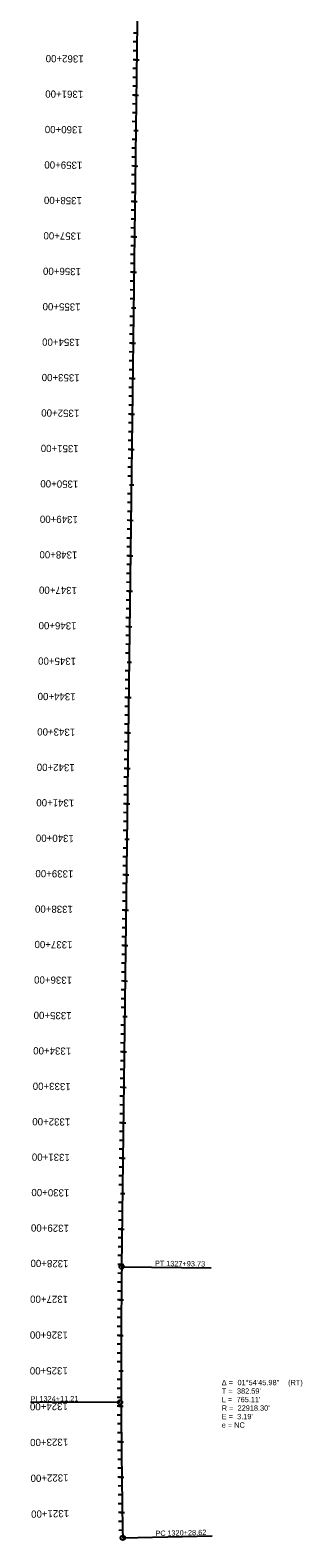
# Model space of a CAD drawing. Extents: x 20505176 to 20507119, y 7960287 to 7982631.
# Drawn here: x 20506353 to 20507119, y 7964831 to 7969085 of the extents above; entities that cross this region are included whole.
import ezdxf

# ---------------------------------------------------------------- set-up
doc = ezdxf.new("R2010")
doc.units = 0
for name, color, linetype in [('Alignment', 7, 'Continuous'), ('Default', 7, 'Continuous'), ('PC_REBAR GL 1', 7, 'Continuous'), ('TextAlignment', 7, 'Continuous'), ('TextAlignmentLrg', 7, 'Continuous'), ('TextAlignmentSml', 7, 'Continuous')]:
    doc.layers.add(name, color=color, linetype=linetype)

msp = doc.modelspace()

# ---------------------------------------------------------------- linework, layer by layer
at = {"layer": 'Alignment'}
msp.add_line((20506611.2, 7965595.6), (20506708.1, 7973298), dxfattribs=at)
msp.add_arc((20529527.7, 7965307.2), 22918.3, 179.27906, 181.19184, dxfattribs=at)
at = {"layer": 'Default'}
msp.add_line((20506611.2, 7965595.6), (20506708.1, 7973298), dxfattribs=at)
msp.add_arc((20529527.7, 7965307.2), 22918.3, 179.27906, 181.19184, dxfattribs=at)
at = {"layer": 'PC_REBAR GL 1'}
msp.add_line((20506611.2, 7965595.6), (20506708.1, 7973298), dxfattribs=at)
msp.add_arc((20529527.7, 7965307.2), 22918.3, 179.27906, 181.19184, dxfattribs=at)
at = {"layer": 'TextAlignment'}
for p, q in [((20506611.2, 7965595.6), (20506863.2, 7965592.4)), ((20506863.2, 7965592.4), (20506863.2, 7965592.4)), ((20506606.4, 7965213), (20506354.4, 7965212)), ((20506354.4, 7965212), (20506354.4, 7965212)), ((20506614.3, 7964830.5), (20506866.3, 7964835.8)), ((20506866.3, 7964835.8), (20506866.3, 7964835.8))]:
    msp.add_line(p, q, dxfattribs=at)
for centre in [(20506611.2, 7965595.6), (20506606.4, 7965213), (20506614.3, 7964830.5)]:
    msp.add_circle(centre, 6.24, dxfattribs=at)
at = {"layer": 'TextAlignmentLrg'}
for p, q in [((20506654, 7969001.6), (20506643.1, 7969001.7)), ((20506652.8, 7968901.6), (20506641.9, 7968901.8)), ((20506645.4, 7968801.7), (20506657.6, 7968801.5)), ((20506650.3, 7968701.6), (20506639.3, 7968701.8)), ((20506649, 7968601.6), (20506638.1, 7968601.8)), ((20506647.8, 7968501.6), (20506636.8, 7968501.8)), ((20506646.5, 7968401.7), (20506635.6, 7968401.8)), ((20506639.1, 7968301.7), (20506651.4, 7968301.6)), ((20506644, 7968201.7), (20506633.1, 7968201.8)), ((20506642.7, 7968101.7), (20506631.8, 7968101.8)), ((20506641.5, 7968001.7), (20506630.5, 7968001.8)), ((20506640.2, 7967901.7), (20506629.3, 7967901.8)), ((20506632.8, 7967801.8), (20506645.1, 7967801.6)), ((20506637.7, 7967701.7), (20506626.8, 7967701.8)), ((20506636.4, 7967601.7), (20506625.5, 7967601.9)), ((20506635.2, 7967501.7), (20506624.3, 7967501.9)), ((20506633.9, 7967401.7), (20506623, 7967401.9)), ((20506626.5, 7967301.8), (20506638.8, 7967301.7)), ((20506631.4, 7967201.7), (20506620.5, 7967201.9)), ((20506630.1, 7967101.8), (20506619.2, 7967101.9)), ((20506628.9, 7967001.8), (20506618, 7967001.9)), ((20506627.6, 7966901.8), (20506616.7, 7966901.9)), ((20506620.2, 7966801.9), (20506632.5, 7966801.7)), ((20506625.1, 7966701.8), (20506614.2, 7966701.9)), ((20506623.8, 7966601.8), (20506612.9, 7966601.9)), ((20506622.6, 7966501.8), (20506611.7, 7966501.9)), ((20506621.3, 7966401.8), (20506610.4, 7966402)), ((20506614, 7966301.9), (20506626.2, 7966301.7)), ((20506618.8, 7966201.8), (20506607.9, 7966202)), ((20506617.6, 7966101.8), (20506606.6, 7966102)), ((20506616.3, 7966001.8), (20506605.4, 7966002)), ((20506615, 7965901.9), (20506604.1, 7965902)), ((20506607.7, 7965801.9), (20506619.9, 7965801.8)), ((20506612.5, 7965701.9), (20506601.6, 7965702)), ((20506611.3, 7965601.9), (20506600.3, 7965602)), ((20506610.2, 7965501.9), (20506599.3, 7965502)), ((20506609.6, 7965401.9), (20506598.6, 7965401.9)), ((20506603.3, 7965301.9), (20506615.5, 7965301.9)), ((20506609.6, 7965201.9), (20506598.7, 7965201.8)), ((20506610.3, 7965101.9), (20506599.4, 7965101.8)), ((20506611.4, 7965001.9), (20506600.5, 7965001.7)), ((20506613, 7964901.9), (20506602, 7964901.7))]:
    msp.add_line(p, q, dxfattribs=at)
at = {"layer": 'TextAlignmentSml'}
for p, q in [((20506654.7, 7969051.6), (20506643.8, 7969051.7)), ((20506655, 7969076.6), (20506644.1, 7969076.7)), ((20506654.4, 7969026.6), (20506643.4, 7969026.7)), ((20506653.7, 7968976.6), (20506642.8, 7968976.7)), ((20506647.9, 7969001.7), (20506660.2, 7969001.5)), ((20506653.1, 7968926.6), (20506642.2, 7968926.8)), ((20506653.4, 7968951.6), (20506642.5, 7968951.7)), ((20506646.7, 7968901.7), (20506658.9, 7968901.5)), ((20506652.2, 7968851.6), (20506641.2, 7968851.8)), ((20506652.5, 7968876.6), (20506641.6, 7968876.8)), ((20506651.8, 7968826.6), (20506640.9, 7968826.8)), ((20506645.4, 7968801.7), (20506657.6, 7968801.5)), ((20506651.2, 7968776.6), (20506640.3, 7968776.8)), ((20506650.6, 7968726.6), (20506639.7, 7968726.8)), ((20506650.9, 7968751.6), (20506640, 7968751.8)), ((20506650, 7968676.6), (20506639, 7968676.8)), ((20506644.1, 7968701.7), (20506656.4, 7968701.6)), ((20506649.3, 7968626.6), (20506638.4, 7968626.8)), ((20506649.6, 7968651.6), (20506638.7, 7968651.8)), ((20506642.9, 7968601.7), (20506655.1, 7968601.6)), ((20506648.4, 7968551.6), (20506637.5, 7968551.8)), ((20506648.7, 7968576.6), (20506637.8, 7968576.8)), ((20506648.1, 7968526.6), (20506637.1, 7968526.8)), ((20506641.6, 7968501.7), (20506653.9, 7968501.6)), ((20506647.4, 7968476.6), (20506636.5, 7968476.8)), ((20506646.8, 7968426.7), (20506635.9, 7968426.8)), ((20506647.1, 7968451.7), (20506636.2, 7968451.8)), ((20506646.2, 7968376.7), (20506635.3, 7968376.8)), ((20506640.4, 7968401.7), (20506652.6, 7968401.6)), ((20506645.9, 7968351.7), (20506634.9, 7968351.8)), ((20506645.5, 7968326.7), (20506634.6, 7968326.8)), ((20506639.1, 7968301.7), (20506651.4, 7968301.6)), ((20506644.6, 7968251.7), (20506633.7, 7968251.8)), ((20506644.9, 7968276.7), (20506634, 7968276.8)), ((20506644.3, 7968226.7), (20506633.4, 7968226.8)), ((20506637.9, 7968201.7), (20506650.1, 7968201.6)), ((20506643.7, 7968176.7), (20506632.7, 7968176.8)), ((20506643, 7968126.7), (20506632.1, 7968126.8)), ((20506643.3, 7968151.7), (20506632.4, 7968151.8)), ((20506642.4, 7968076.7), (20506631.5, 7968076.8)), ((20506636.6, 7968101.8), (20506648.8, 7968101.6)), ((20506642.1, 7968051.7), (20506631.2, 7968051.8)), ((20506641.8, 7968026.7), (20506630.9, 7968026.8)), ((20506635.3, 7968001.8), (20506647.6, 7968001.6)), ((20506640.8, 7967951.7), (20506629.9, 7967951.8)), ((20506641.1, 7967976.7), (20506630.2, 7967976.8)), ((20506640.5, 7967926.7), (20506629.6, 7967926.8)), ((20506634.1, 7967901.8), (20506646.3, 7967901.6)), ((20506639.9, 7967876.7), (20506629, 7967876.8)), ((20506639.3, 7967826.7), (20506628.3, 7967826.8)), ((20506639.6, 7967851.7), (20506628.7, 7967851.8)), ((20506638.6, 7967776.7), (20506627.7, 7967776.8)), ((20506632.8, 7967801.8), (20506645.1, 7967801.6)), ((20506638.3, 7967751.7), (20506627.4, 7967751.8)), ((20506638, 7967726.7), (20506627.1, 7967726.8)), ((20506631.6, 7967701.8), (20506643.8, 7967701.6)), ((20506637.1, 7967651.7), (20506626.1, 7967651.9)), ((20506637.4, 7967676.7), (20506626.5, 7967676.8)), ((20506636.7, 7967626.7), (20506625.8, 7967626.9)), ((20506636.1, 7967576.7), (20506625.2, 7967576.9)), ((20506630.3, 7967601.8), (20506642.5, 7967601.6)), ((20506635.5, 7967526.7), (20506624.6, 7967526.9)), ((20506635.8, 7967551.7), (20506624.9, 7967551.9)), ((20506634.9, 7967476.7), (20506623.9, 7967476.9)), ((20506629, 7967501.8), (20506641.3, 7967501.6)), ((20506634.5, 7967451.7), (20506623.6, 7967451.9)), ((20506634.2, 7967426.7), (20506623.3, 7967426.9)), ((20506627.8, 7967401.8), (20506640, 7967401.7)), ((20506633.3, 7967351.7), (20506622.4, 7967351.9)), ((20506633.6, 7967376.7), (20506622.7, 7967376.9)), ((20506633, 7967326.7), (20506622, 7967326.9)), ((20506632.3, 7967276.7), (20506621.4, 7967276.9)), ((20506626.5, 7967301.8), (20506638.8, 7967301.7)), ((20506631.7, 7967226.7), (20506620.8, 7967226.9)), ((20506632, 7967251.7), (20506621.1, 7967251.9)), ((20506625.3, 7967201.8), (20506637.5, 7967201.7)), ((20506630.8, 7967151.8), (20506619.8, 7967151.9)), ((20506631.1, 7967176.8), (20506620.2, 7967176.9)), ((20506630.5, 7967126.8), (20506619.5, 7967126.9)), ((20506624, 7967101.8), (20506636.3, 7967101.7)), ((20506629.5, 7967051.8), (20506618.6, 7967051.9)), ((20506629.8, 7967076.8), (20506618.9, 7967076.9)), ((20506629.2, 7967026.8), (20506618.3, 7967026.9)), ((20506628.6, 7966976.8), (20506617.6, 7966976.9)), ((20506622.8, 7967001.8), (20506635, 7967001.7)), ((20506627.9, 7966926.8), (20506617, 7966926.9)), ((20506628.2, 7966951.8), (20506617.3, 7966951.9)), ((20506621.5, 7966901.9), (20506633.7, 7966901.7)), ((20506627, 7966851.8), (20506616.1, 7966851.9)), ((20506627.3, 7966876.8), (20506616.4, 7966876.9)), ((20506626.7, 7966826.8), (20506615.8, 7966826.9)), ((20506620.2, 7966801.9), (20506632.5, 7966801.7)), ((20506626, 7966776.8), (20506615.1, 7966776.9)), ((20506625.4, 7966726.8), (20506614.5, 7966726.9)), ((20506625.7, 7966751.8), (20506614.8, 7966751.9)), ((20506624.8, 7966676.8), (20506613.9, 7966676.9)), ((20506619, 7966701.9), (20506631.2, 7966701.7)), ((20506624.2, 7966626.8), (20506613.2, 7966626.9)), ((20506624.5, 7966651.8), (20506613.6, 7966651.9)), ((20506617.7, 7966601.9), (20506630, 7966601.7)), ((20506623.2, 7966551.8), (20506612.3, 7966551.9)), ((20506623.5, 7966576.8), (20506612.6, 7966576.9)), ((20506622.9, 7966526.8), (20506612, 7966526.9)), ((20506616.5, 7966501.9), (20506628.7, 7966501.7)), ((20506622.3, 7966476.8), (20506611.4, 7966476.9)), ((20506621.6, 7966426.8), (20506610.7, 7966426.9)), ((20506622, 7966451.8), (20506611, 7966451.9)), ((20506621, 7966376.8), (20506610.1, 7966377)), ((20506615.2, 7966401.9), (20506627.4, 7966401.7)), ((20506620.7, 7966351.8), (20506609.8, 7966352)), ((20506620.4, 7966326.8), (20506609.5, 7966327)), ((20506614, 7966301.9), (20506626.2, 7966301.7)), ((20506619.4, 7966251.8), (20506608.5, 7966252)), ((20506619.8, 7966276.8), (20506608.8, 7966277)), ((20506619.1, 7966226.8), (20506608.2, 7966227)), ((20506612.7, 7966201.9), (20506624.9, 7966201.8)), ((20506618.5, 7966176.8), (20506607.6, 7966177)), ((20506617.9, 7966126.8), (20506606.9, 7966127)), ((20506618.2, 7966151.8), (20506607.3, 7966152)), ((20506617.2, 7966076.8), (20506606.3, 7966077)), ((20506611.4, 7966101.9), (20506623.7, 7966101.8)), ((20506616.9, 7966051.8), (20506606, 7966052)), ((20506616.6, 7966026.8), (20506605.7, 7966027)), ((20506610.2, 7966001.9), (20506622.4, 7966001.8)), ((20506615.7, 7965951.8), (20506604.7, 7965952)), ((20506616, 7965976.8), (20506605.1, 7965977)), ((20506615.4, 7965926.9), (20506604.4, 7965927)), ((20506608.9, 7965901.9), (20506621.2, 7965901.8)), ((20506614.7, 7965876.9), (20506603.8, 7965877)), ((20506614.1, 7965826.9), (20506603.2, 7965827)), ((20506614.4, 7965851.9), (20506603.5, 7965852)), ((20506613.5, 7965776.9), (20506602.5, 7965777)), ((20506607.7, 7965801.9), (20506619.9, 7965801.8)), ((20506613.2, 7965751.9), (20506602.2, 7965752)), ((20506612.8, 7965726.9), (20506601.9, 7965727)), ((20506606.4, 7965701.9), (20506618.6, 7965701.8)), ((20506611.9, 7965651.9), (20506601, 7965652)), ((20506612.2, 7965676.9), (20506601.3, 7965677)), ((20506611.6, 7965626.9), (20506600.7, 7965627)), ((20506611, 7965576.9), (20506600, 7965577)), ((20506605.1, 7965602), (20506617.4, 7965601.8)), ((20506610.4, 7965526.9), (20506599.5, 7965527)), ((20506610.7, 7965551.9), (20506599.8, 7965552)), ((20506610, 7965476.9), (20506599.1, 7965477)), ((20506604.1, 7965501.9), (20506616.3, 7965501.8)), ((20506609.8, 7965451.9), (20506598.9, 7965452)), ((20506609.7, 7965426.9), (20506598.8, 7965426.9)), ((20506603.4, 7965401.9), (20506615.7, 7965401.9)), ((20506609.4, 7965351.9), (20506598.5, 7965351.9)), ((20506609.5, 7965376.9), (20506598.6, 7965376.9)), ((20506609.4, 7965326.9), (20506598.5, 7965326.9)), ((20506609.4, 7965276.9), (20506598.5, 7965276.9)), ((20506603.3, 7965301.9), (20506615.5, 7965301.9)), ((20506609.4, 7965251.9), (20506598.5, 7965251.9)), ((20506609.5, 7965226.9), (20506598.6, 7965226.8)), ((20506603.5, 7965201.9), (20506615.7, 7965201.9)), ((20506609.7, 7965176.9), (20506598.8, 7965176.8)), ((20506609.9, 7965151.9), (20506599, 7965151.8)), ((20506610.1, 7965126.9), (20506599.2, 7965126.8)), ((20506604.2, 7965101.8), (20506616.4, 7965101.9)), ((20506610.5, 7965076.9), (20506599.6, 7965076.8)), ((20506610.8, 7965051.9), (20506599.9, 7965051.8)), ((20506611.1, 7965026.9), (20506600.2, 7965026.8)), ((20506611.8, 7964976.9), (20506600.8, 7964976.7)), ((20506605.3, 7965001.8), (20506617.5, 7965002)), ((20506612.1, 7964951.9), (20506601.2, 7964951.7)), ((20506612.5, 7964926.9), (20506601.6, 7964926.7)), ((20506606.8, 7964901.8), (20506619.1, 7964902)), ((20506613.4, 7964876.9), (20506602.5, 7964876.7)), ((20506613.9, 7964851.9), (20506603, 7964851.7))]:
    msp.add_line(p, q, dxfattribs=at)

# ---------------------------------------------------------------- texts
at = {"layer": 'TextAlignment'}
for s, rotation, p in [('PT', 359.2791, (20506704.8, 7965597.7)), ('1327+93.73', 359.2791, (20506736.3, 7965597.3)), ('PI ', 0.2354, (20506354.4, 7965215.3)), ('1324+11.21', 0.2354, (20506379.4, 7965215.4)), ('PC', 1.1918, (20506706.4, 7964835.7)), ('1320+28.62', 1.1918, (20506739.8, 7964836.4))]:
    msp.add_text(s, height=15, rotation=rotation, dxfattribs=at).set_placement(p)
for s, p in [('Δ = ', (20506893, 7965261.3)), ('01°54\'45.98"', (20506937.4, 7965261.3)), (' (RT)', (20507074.1, 7965261.3)), ('T = ', (20506893, 7965237.3)), ('L = ', (20506893, 7965213.3)), ("765.11'", (20506934.8, 7965213.3)), ("382.59'", (20506935.9, 7965237.3)), ('R = ', (20506893, 7965189.3)), ('E = ', (20506893, 7965165.3)), ("3.19'", (20506936.3, 7965165.3)), ("22918.30'", (20506937.6, 7965189.3)), ('e = NC', (20506893, 7965141.3))]:
    msp.add_text(s, height=15, dxfattribs=at).set_placement(p)
at = {"layer": 'TextAlignmentLrg'}
for s, rotation, p in [('1360+00', 179.2791, (20506501.7, 7968813.7)), ('1355+00', 179.2791, (20506495.4, 7968313.7)), ('1350+00', 179.2791, (20506489.1, 7967813.8)), ('1345+00', 179.2791, (20506482.8, 7967313.8)), ('1340+00', 179.2791, (20506476.5, 7966813.9)), ('1335+00', 179.2791, (20506470.2, 7966313.9)), ('1330+00', 179.2791, (20506463.9, 7965813.9)), ('1325+00', 180.0134, (20506459.4, 7965312))]:
    msp.add_text(s, height=20.4, rotation=rotation, dxfattribs=at).set_placement(p)
at = {"layer": 'TextAlignmentSml'}
for s, rotation, p in [('1362+00', 179.2791, (20506504.2, 7969013.7)), ('1361+00', 179.2791, (20506502.9, 7968913.7)), ('1360+00', 179.2791, (20506501.7, 7968813.7)), ('1359+00', 179.2791, (20506500.4, 7968713.7)), ('1358+00', 179.2791, (20506499.2, 7968613.7)), ('1357+00', 179.2791, (20506497.9, 7968513.7)), ('1356+00', 179.2791, (20506496.6, 7968413.7)), ('1355+00', 179.2791, (20506495.4, 7968313.7)), ('1354+00', 179.2791, (20506494.1, 7968213.8)), ('1353+00', 179.2791, (20506492.9, 7968113.8)), ('1352+00', 179.2791, (20506491.6, 7968013.8)), ('1351+00', 179.2791, (20506490.3, 7967913.8)), ('1350+00', 179.2791, (20506489.1, 7967813.8)), ('1349+00', 179.2791, (20506487.8, 7967713.8)), ('1348+00', 179.2791, (20506486.6, 7967613.8)), ('1347+00', 179.2791, (20506485.3, 7967513.8)), ('1346+00', 179.2791, (20506484.1, 7967413.8)), ('1345+00', 179.2791, (20506482.8, 7967313.8)), ('1344+00', 179.2791, (20506481.5, 7967213.8)), ('1343+00', 179.2791, (20506480.3, 7967113.8)), ('1342+00', 179.2791, (20506479, 7967013.9)), ('1341+00', 179.2791, (20506477.8, 7966913.9)), ('1340+00', 179.2791, (20506476.5, 7966813.9)), ('1339+00', 179.2791, (20506475.2, 7966713.9)), ('1338+00', 179.2791, (20506474, 7966613.9)), ('1337+00', 179.2791, (20506472.7, 7966513.9)), ('1336+00', 179.2791, (20506471.5, 7966413.9)), ('1335+00', 179.2791, (20506470.2, 7966313.9)), ('1334+00', 179.2791, (20506469, 7966213.9)), ('1333+00', 179.2791, (20506467.7, 7966113.9)), ('1332+00', 179.2791, (20506466.4, 7966013.9)), ('1331+00', 179.2791, (20506465.2, 7965913.9)), ('1330+00', 179.2791, (20506463.9, 7965813.9)), ('1329+00', 179.2791, (20506462.7, 7965714)), ('1328+00', 179.2791, (20506461.4, 7965614)), ('1327+00', 179.5134, (20506460.3, 7965513.4)), ('1326+00', 179.7634, (20506459.6, 7965412.7)), ('1325+00', 180.0134, (20506459.4, 7965312)), ('1324+00', 180.2634, (20506459.6, 7965211.4)), ('1323+00', 180.5134, (20506460.2, 7965110.7)), ('1322+00', 180.7634, (20506461.3, 7965010.1)), ('1321+00', 181.0134, (20506462.8, 7964909.5))]:
    msp.add_text(s, height=20.4, rotation=rotation, dxfattribs=at).set_placement(p)

doc.saveas('drawing.dxf')
